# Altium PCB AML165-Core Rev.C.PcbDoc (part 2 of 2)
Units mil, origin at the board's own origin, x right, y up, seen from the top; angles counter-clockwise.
Board outline 3307.09 x 2047.24 mil, 2 copper layers (Top Layer, Bottom Layer), stack 12.8 mil thick; 150 components, 70 nets, 398 pads, 304 vias.
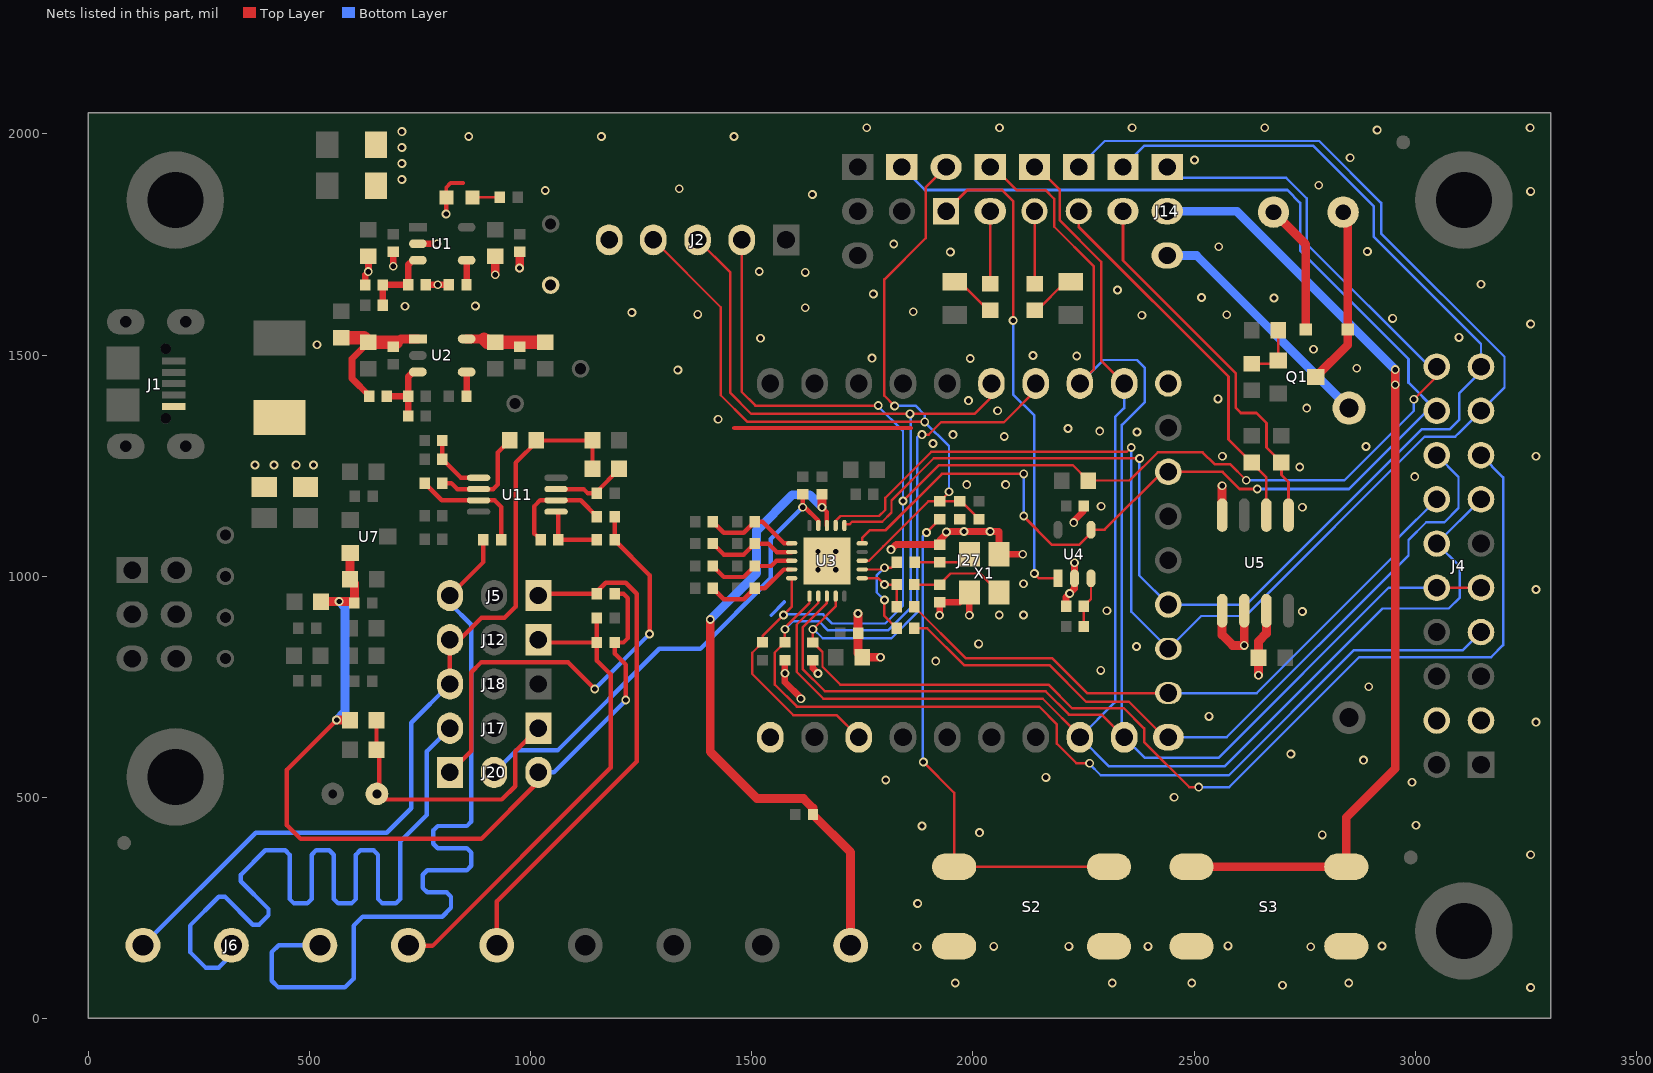
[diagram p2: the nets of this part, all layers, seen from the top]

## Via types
v1: diameter 20, hole 12, Top Layer to Bottom Layer, tented both sides, 304 vias

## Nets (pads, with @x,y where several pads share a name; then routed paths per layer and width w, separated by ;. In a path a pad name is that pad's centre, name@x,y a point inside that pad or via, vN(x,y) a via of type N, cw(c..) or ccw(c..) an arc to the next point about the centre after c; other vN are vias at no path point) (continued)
GND: BZ1.2 C1.2 C2.1 C3.2 C4.1 C5.1 C6.1 C18.1 C19.1 C21.2 C22.1 C25.1 C26.1 C32.2 C34.2 C43.1 D1.2 D2.1 J1.5 J2.5 J4.3 J4.4 J27.1 J27.18 LED1.2 R3.2 R6.1 R7.1 R9.1 R18.2 R42.1 S2.1 S2.4 S3.1 S3.4 T2.1 U1.2 U3.21 U4.2 U5.4 U5.5 U5.6 U5.7 X1.2 X1.4 | length 2518.1
  Top Layer w8: LED1.2@809.71,1856.54 809.71,1879.62 819,1888.91 848,1888.91
  Top Layer w10: v1(633,1688.54) v1@633.35,1688.88 ; v1(809,1818.91) 809,1855.82 LED1.2@809.71,1856.54 ; 1460,1334.91 1859.75,1335
  Top Layer w15: R3.2@626.03,1658.46 626.03,1681.57 v1(633,1688.54) ; v1@633.35,1688.88 C1.2@633.35,1723.5 ; v1(689.49,1700.54) C2.1@689.49,1733.5 ; U1.2@745.21,1751.54 v1(789,1751.54) ; C6.1@762.97,1659.02 v1(790.12,1659.02) C5.1@815,1659.02 ; R18.2@1575,810.32 v1(1575,780.43) 1575,760.16 1611,724.16 v1(1611,722.91) ; R9.1@1638.2,810 1638.2,791.8 v1(1650,780) ; v1(1815,1060) 1826.39,1071.39 C21.2@1924.82,1071.39 1924.82,1080.9 1940,1096.09 v1(1940,1099.91) 1941,1100.91 v1(1980,1100.91) v1(2039.03,1100.91) 2059.03,1100.91 X1.2@2059.03,1049.63 v1(2112.67,1049.63) ; v1@1924.82,911.51 C22.1@1924.82,941.02 1970.11,941.02 X1.4@1992.1,963.01 v1(1992.1,911.73) ; C26.1@2210.63,931.8 2210.63,952.77 v1(2218.77,960.91) 2229.72,971.85 U4.2@2229.72,994.93 v1(2229.72,1030.19) ; v1(2228,1120.92) 2228,1124.91 2250.63,1147.54 C25.1@2250.63,1158.54
  Top Layer w20: v1(920,1681.54) C3.2@920,1723.5 ; v1(975,1696.54) 975.52,1697.05 C4.1@975.52,1733.5 ; v1(1740.32,915.59) C18.1@1740.32,871.02 1740.32,826.28 C19.1@1750,816.59 v1(1791.32,816.59) ; U5.5@2563.63,945.28 U5.5@2563.63,921.97 2563.63,867.28 2587.37,843.54 v1(2613.63,843.54) U5.6@2613.63,921.97 ; U5.4@2563.63,1138.03 v1(2563.63,1204.28) ; v1(2645.91,776) C34.2@2645.91,815.91 2645.91,852.81 2663.63,870.54 U5.7@2663.63,921.97 ; BZ1.2@2679.81,1822.87 2752.5,1750.19 D2.1@2752.5,1557.76
  Bottom Layer w8: 1544,911.91 1574,941.91
  other v1: 3261,69.91 2700,75 1960,80 2315,80 2495,80 2850,80 1874,161.91 2764,162 2047,162.91 2217,162.91 2396,162.91 2577,164 2925,163.91 1875,260 3261,369.91 2790,415 2015,420 1885,435 3002,436.91 2455,500 2993,533.91 1803,538.91 2165,545 2883,583.91 2719,597.91 3273,669.91 2534,682.91 2895,749.91 2289,786.91 1916,807.91 2370,840.91 2013,846.91 1924.64,911.51 2059.57,911.96 2114.44,911.96 2745,919.91 2303,921.91 3273,969.91 2114.22,982.81 1650,1014.39 1690,1014.39 1650,1055.91 1690,1055.91 2745,1155.91 2290,1158 1986,1206.91 2074,1206.91 2999,1224.91 2739,1246.91 376.92,1251.09 419.92,1251.09 469.92,1251.09 508.92,1251.09 2564,1270.91 3273,1270.91 2889,1292.91 1910,1300 2071,1315.91 1955,1319.91 2371,1325.91 2287,1327.91 2215,1333.91 1424,1354.91 2056,1373.91 2755,1379.91 1990,1396.91 2554,1400.91 1333,1465.91 2868,1469.91 1994,1491.91 1772,1492.91 2235,1497.91 2136,1498.91 2770,1512.91 516.92,1523.09 1520,1537.91 3099,1539.91 3261,1569.91 2949,1582.91 2382,1589.91 2574,1590.91 1378,1591.91 1229,1595.91 1865,1597.91 1621,1606.91 715.92,1610.09 875,1610.91 2681,1628.91 2517,1629.91 1775,1637.91 2327,1646.91 3149,1660 1621,1686.91 1517,1688.91 1949,1732.91 2892,1734 2556,1744.91 1821,1750.91 1637,1862.91 3261,1869.91 1033,1871.91 1336,1875.91 2782,1883.91 708.93,1896.88 708.93,1932.92 2501,1940.91 2853,1945.91 708.93,1968.96 860,1994.22 1160,1994.22 1460,1994.22 708.93,2005 2914,2008.91 1760,2013.91 2060,2013.91 2360,2013.91 2660,2013.91 3260,2013.91
GPIO_KEY: J2.2 J4.20 J14.1 J27.3 R17.2 R41.1 U3.5 | length 4289.1
  Top Layer w5.5: J2.2@1477.48,1760.47 1477.48,1416.43 1508.21,1385.7 v1(1786,1385.7) ; U3.5@1590.28,995.4 1590.28,930.2 v1(1572,911.93) 1524.48,864.41 R17.2@1524.48,850.32 1501,826.84 1501,778.8 1593.9,685.91 1691.77,685.91 J27.3@1741.98,635.7 ; v1(1842,1169.91) 1923.07,1250.97 2225.86,1250.97 R41.1@2260.63,1216.2 2354.29,1216.2 2418,1279.91 2519.5,1279.91 2546.25,1253.16 2581.75,1253.16 v1(2618,1216.91) ; v1(2997,1399.91) 3048.82,1451.72 J4.20@3048.82,1473.62
  Bottom Layer w5.5: v1(1572,911.93) 1573.48,913.41 1661.36,913.41 1681.86,892.91 1801.75,892.91 1842,933.15 v1(1842,1169.91) 1842,1327.91 1786,1383.91 v1(1786,1385.7) ; J14.1@2439.37,1925 2463.46,1900.91 2708.09,1900.91 2755,1854 2755,1750.91 3032.28,1473.62 J4.20@3048.82,1473.62 ; v1(2618,1216.91) 2840,1216.91 2997,1373.91 v1(2997,1399.91)
GPIO_LED0: J4.9 J4.10 J9.1 J27.9 J27.20 U3.8 | length 3640.9
  Top Layer w5.5: U3.8@1670,955.05 1670,938.91 1615,883.91 1615,789.9 1665.26,739.63 2164.27,739.63 2217,686.91 2290.77,686.91 J27.9@2341.98,635.7 ; J9.1@2039.37,1925 2046.91,1925 2099,1872.91 2164,1872.91 2184,1852.91 2184,1789.91 2273,1700.91 2273,1466.72 J27.20@2241.98,1435.7 ; J4.10@3048.82,973.62 J4.9@3148.82,973.62
  Bottom Layer w5.5: J27.20@2241.98,1435.7 2294.93,1488.66 2371.25,1488.66 2389,1470.91 2389,1393.91 2337,1341.91 2337,640.68 J27.9@2341.98,635.7 2388.77,588.91 2555,588.91 2939.72,973.62 J4.10@3048.82,973.62
GPIO_LED1: J4.12 J4.13 J10.1 J27.8 J27.19 U3.7 | length 3642.7
  Top Layer w5.5: U3.7@1650.32,955.05 1650.32,939.22 1601.27,890.18 1601.27,783.73 1662.09,722.91 2158,722.91 2241.98,638.93 J27.8@2241.98,635.7 ; J10.1@2139.37,1925 2144.91,1925 2196,1873.91 2196,1804.91 2290,1710.91 2290,1487.68 J27.19@2341.98,1435.7
  Bottom Layer w5.5: J27.19@2341.98,1435.7 2341.98,1379.88 2321.53,1359.44 2321.53,715.26 J27.8@2241.98,635.7 2307.77,569.91 2569,569.91 2926,926.91 3076,926.91 3101,951.91 3101,1021.44 J4.12@3048.82,1073.62 J4.13@3148.82,1173.62
LED0: J9.2 R29.2 | length 164.3
  Top Layer w5.5: R29.2@2038.78,1660.91 2039.37,1661.49 J9.2@2039.37,1825
LED1: J10.2 R35.2 | length 164.4
  Top Layer w5.5: J10.2@2139.37,1825 2140,1824.37 R35.2@2140,1660.91
LM75_SCL: J4.17 J11.1 J27.12 U3.17 | length 3556.8
  Top Layer w5.5: U3.17@1689.69,1114.5 1689.69,1124.69 1701,1136 1788.11,1136 1801.87,1149.76 1801.87,1176.85 1906.24,1281.22 2348.32,1281.22 v1(2358,1290.91)
  Bottom Layer w5.5: J11.1@2239.37,1925 2298.28,1983.91 2783.04,1983.91 2923,1843.95 2923,1774.91 3202,1495.91 3202,1426.8 J4.17@3148.82,1373.62 3101.1,1325.91 3101,1325.91 3090.41,1315.31 3021.41,1315.31 2616,909.91 2516.18,909.91 J27.12@2441.98,835.7 2358,919.68 v1(2358,1290.91)
LM75_SDA: J4.19 J13.1 J27.13 U3.16 | length 3182
  Top Layer w5.5: U3.16@1709.37,1114.5 1711.87,1117 1721,1117 1727,1123 1795.09,1123 1816,1143.91 1816,1171 1911.41,1266.41 2376.49,1266.41 v1(2377,1265.91)
  Bottom Layer w5.5: J13.1@2339.37,1925 2387.28,1972.91 2770,1972.91 2906,1836.91 2906,1767.86 3148.82,1525.04 J4.19@3148.82,1473.62 3148.82,1462.72 3100,1413.91 3100,1353.91 3077.84,1331.74 3014.6,1331.74 2618.56,935.7 J27.13@2441.98,935.7 2376,1001.68 v1@2376,1265.91
MICROPORT_ADC1: J4.18 J7.1 J27.16 U3.15 U4.4 | length 3188.4
  Top Layer w6: U3.15@1749.72,1074.14 1749.72,1086.72 1766.91,1103.91 1803,1103.91 1930.32,1231.22 v1(2115,1231.22) ; v1(2115,1135.91) 2115,1134.94 2179.04,1070.91 2240,1070.91 2267.12,1098.02 U4.4@2267.12,1104.93 2297.56,1104.93 2428.33,1235.7 J27.16@2441.98,1235.7 2564.21,1235.7 2603,1196.91 v1(2643,1196.91)
  Bottom Layer w6: J7.1@1839.37,1925 1891.46,1872.91 2711.09,1872.91 2740,1844 2740,1735.91 2985,1490.91 2985,1437.44 J4.18@3048.82,1373.62 3026.64,1373.62 2849.93,1196.91 v1(2643,1196.91) ; v1(2115,1135.91) v1(2115,1231.22)
MICROPORT_CS: J2.3 J4.7 J27.22 R18.1 U3.6 | length 3869.9
  Top Layer w5.5: J2.3@1377.48,1760.47 1451.78,1686.17 1451.78,1414.13 1499,1366.91 v1(1858,1366.91) 2004,1366.91 2041.98,1404.88 J27.22@2041.98,1435.7 ; U3.6@1630.63,955.05 1630.63,939.54 1575,883.91 v1(1575,879.91) R18.1@1575,850.32 1552,827.32 1552,754.91 1602,704.91 2150,704.91 2190,664.91 2190,620.91 2234,576.91 v1(2264,576.91)
  Bottom Layer w5.5: v1(1575,879.91) 1593,897.91 1652,897.91 1672.66,877.25 1808.24,877.25 1859.75,928.76 1859.75,1365.16 v1(1858,1366.91) ; v1(2264,576.91) 2264,574.91 2289,549.91 2579,549.91 2862,832.91 3108.1,832.91 J4.7@3148.82,873.62
MICROPORT_I/O2: J4.14 J27.11 R21.1 | length 1461.6
  Top Layer w5.5: R21.1@1867.56,930.91 1984.56,813.91 2180,813.91 2258.21,735.7 J27.11@2441.98,735.7
  Bottom Layer w5.5: J27.11@2441.98,735.7 2641.79,735.7 2960,1053.91 2960,1084.8 J4.14@3048.82,1173.62
MICROPORT_I/O3: J4.16 J27.10 R19.1 | length 1707.8
  Top Layer w5.5: R19.1@1867.56,882.28 1896.63,882.28 1980,798.91 2173,798.91 2256,715.91 2353,715.91 2433.21,635.7 J27.10@2441.98,635.7
  Bottom Layer w5.5: J27.10@2441.98,635.7 2573.79,635.7 2985,1046.91 2985,1081.91 3025,1121.91 3066,1121.91 3098,1153.91 3098,1224.44 J4.16@3048.82,1273.62
MICROPORT_MOSI: J4.15 J27.21 R9.2 U3.9 | length 3435.7
  Top Layer w5.5: U3.9@1689.69,955.05 1689.69,931.39 v1(1638.2,879.91) R9.2@1638.2,850 1660,828.2 1660,795.1 1700.2,754.91 2171,754.91 2224.5,701.41 2341.5,701.41 2387,655.91 2387,625.13 2489.22,522.91 v1(2510.61,522.91) ; v1(1885,1320) 1900.09,1320 1928,1347.91 2070,1347.91 2141.98,1419.88 J27.21@2141.98,1435.7
  Bottom Layer w5.5: v1(1638.2,879.91) 1640,879.91 1660.41,859.5 1815.59,859.5 1874,917.91 1874,1314 1880,1320 v1(1885,1320) ; v1(2510.61,522.91) 2579.62,522.91 2873.62,816.91 3172,816.91 3199,843.91 3199,1223.44 J4.15@3148.82,1273.62
NetBZ1_1: BZ1.1 D2.2 Q1.3 | length 406.3
  Top Layer w20: Q1.3@2775.5,1450.59 2847.5,1522.6 D2.2@2847.5,1557.76 2847.5,1812.67 BZ1.1@2837.29,1822.87
NetC5_2: C5.2 U1.4 | length 55.2
  Top Layer w15: C5.2@855,1659.02 855.21,1659.23 U1.4@855.21,1714.13
NetC6_2: C6.2 R1.2 R3.1 U1.3 | length 174.2
  Top Layer w15: R1.2@666.03,1612.57 R3.1@666.03,1658.46 666.58,1659.02 C6.2@722.97,1659.02 722.97,1703.5 733.6,1714.13 U1.3@745.21,1714.13
NetC7_1: C7.1 C8.2 L1.2 R4.1 U2.1 | length 345.4
  Top Layer w15: C7.1@633.35,1528.91 596,1491.56 596,1446.91 635,1407.91 R4.1@635,1406.84
  Top Layer w20: C8.2@689.49,1518.91 706.9,1536.31 U2.1@745.21,1536.31
  Top Layer w30: L1.2@571.87,1538.91 623.35,1538.91 C7.1@633.35,1528.91 C8.2@696.54,1528.91
NetC9_1: C9.1 C10.2 L2.1 U2.5 | length 190.1
  Top Layer w20: U2.5@855.21,1536.31 894.6,1536.31 ; C10.2@975.52,1518.91 C10.2@975.52,1528.39
  Top Layer w30: 894.6,1536.31 902,1528.91 C9.1@920,1528.91 L2.1@1032.76,1528.91
NetC11_2: C11.2 U2.4 | length 54.7
  Top Layer w15: C11.2@855,1406.84 855.21,1407.05 U2.4@855.21,1461.5
NetC12_2: C12.2 R4.2 R5.1 U2.3 | length 163.2
  Top Layer w15: R4.2@675,1406.84 C12.2@722.97,1406.84 C12.2@723.12,1406.84 ; R5.1@723.12,1362 C12.2@723.12,1406.84 ; U2.3@745.21,1461.5 734.22,1461.5 723.12,1450.41 C12.2@723.12,1406.84
NetC16_2: C16.2 R8.2 U3.1 | length 219.1
  Top Layer w10: R8.2@1411.91,1122.77 1436.78,1097.91 1482.05,1097.91 C16.2@1506.91,1122.77 1524.23,1122.77 1572.86,1074.14 U3.1@1590.28,1074.14
NetC17_2: C17.2 R12.2 U3.2 | length 206.9
  Top Layer w10: R12.2@1411.91,1073.68 1436.78,1048.81 1482.05,1048.81 C17.2@1506.91,1073.68 1537.32,1073.68 1556.54,1054.46 U3.2@1590.28,1054.46
NetC21_1: C21.1 R11.2 X1.3 | length 131.3
  Top Layer w6: R11.2@1868.35,1031.39 C21.1@1924.82,1031.39 1973.87,1031.39 X1.3@1992.1,1049.63
NetC22_2: C22.2 R14.1 X1.1 | length 219.6
  Top Layer w5.5: R14.1@1867.56,980.91 1924.7,980.91 C22.2@1924.82,981.02 1949.7,1005.91 2016.14,1005.91 X1.1@2059.03,963.01
NetC23_2: C23.2 R13.2 U3.3 | length 203.9
  Top Layer w10: R13.2@1411.91,1022.96 1436.78,998.09 1482.05,998.09 C23.2@1506.91,1022.96 1543.96,1022.96 1555.77,1034.77 U3.3@1590.28,1034.77
NetC24_2: C24.2 R16.2 U3.4 | length 216.6
  Top Layer w10: R16.2@1411.91,972.61 1436.78,947.74 1482.05,947.74 C24.2@1506.91,972.61 1529.61,972.61 1572.09,1015.09 U3.4@1590.28,1015.09
NetC26_2: C26.2 R26.1 U4.3 | length 115.5
  Top Layer w5.5: R26.1@2250.63,886.29 C26.2@2250.63,931.8 2267.12,948.29 U4.3@2267.12,994.93
NetC27_1: C27.1 R24.1 U11.6 | length 245.7
  Top Layer w10: C27.1@800.37,1209.73 821.01,1209.73 833.86,1196.88 U11.6@882.34,1196.88 915.38,1196.88 925.62,1207.12 925.62,1279.54 R24.1@952.85,1306.77
NetC27_2: C27.2 R25.2 U11.7 | length 269.4
  Top Layer w10: C27.2@760.37,1209.73 798.8,1171.29 U11.7@882.34,1171.29 918.45,1171.29 933.35,1156.39 R25.2@933.35,1082.09
NetC36_1: C36.1 R30.2 U11.3 | length 173.2
  Top Layer w10: U11.3@1057.53,1196.88 1119.82,1196.88 1129.62,1187.09 C36.1@1149.93,1187.09 1149.93,1191.41 1199.93,1241.41 R30.2@1199.93,1243.09
NetC39_1: C39.1 R50.2 U11.2 | length 244.1
  Top Layer w10: C39.1@1022.76,1082.09 1008.62,1096.23 1008.62,1158.49 1021.42,1171.29 U11.2@1057.53,1171.29 1113.23,1171.29 R50.2@1149.93,1134.59
NetC39_2: C39.2 R48.1 U11.1 | length 153
  Top Layer w10: U11.1@1057.53,1145.7 1062.76,1140.48 C39.2@1062.76,1082.09 R48.1@1149.93,1082.09
NetJ14_2: J14.2 S3.2 S3.3 | length 2217.7
  Top Layer w20: S3.3@2494.25,343 S3.2@2844.25,343 2844.25,454.25 2955,565 v1(2955,1432.91) v1(2955,1466.91)
  Bottom Layer w20: J14.2@2439.37,1825 2596.91,1825 v1(2955,1466.91) v1(2955,1432.91)
NetJ14_3: J14.3 R40.2 | length 554.2
  Bottom Layer w20: J14.3@2439.37,1725 2505.63,1725 R40.2@2850.63,1380
NetLED1_1: LED1.1 R2.1 | length 61.8
  Top Layer w5.5: LED1.1@868.77,1856.54 R2.1@930.57,1856.54
NetLED2_2: LED2.2 R29.1 | length 106.9
  Top Layer w5.5: LED2.2@1958.78,1665.92 1969.98,1665.92 2035,1600.91 R29.1@2038.78,1600.91
NetLED3_2: LED3.2 R35.1 | length 109.6
  Top Layer w5.5: R35.1@2140,1600.91 2145,1600.91 2210.02,1665.92 LED3.2@2221,1665.92 LED3.2@2222.66,1665.92
NetQ1_1: Q1.1 R28.1 R34.2 | length 130.7
  Top Layer w6: R28.1@2630.91,1480.41 2682.91,1480.41 Q1.1@2690.5,1487.99 2690.5,1555.85 R34.2@2690.44,1555.91
NetR23_2: R23.2 R31.2 U11.5 | length 145.4
  Top Layer w10: R31.2@799.85,1259.89 R31.2@800.37,1259.37 ; R23.2@800.37,1306.77 R31.2@800.37,1264.25 R31.2@800.37,1259.37 ; U11.5@882.34,1222.47 842.47,1222.47 805.57,1259.37 R31.2@800.37,1259.37
NetR27_1: R27.1 S2.2 S2.3 | length 1181.3
  Top Layer w5.5: v1(1888,579.91) 1957.6,510.31 S2.3@1957.6,343 S2.2@2307.6,343 ; v1(1895,1098.83) R27.1@1925.26,1129.09
  Bottom Layer w5.5: v1(1888,579.91) 1886.89,581.02 1886.89,1090.72 v1(1895,1098.83)
NRST_WDT: J8.1 U4.1 | length 1101.6
  Top Layer w6: J8.1@1939.37,1825 1987.27,1872.91 2066,1872.91 2091,1847.91 v1(2091,1577.91) ; v1(2139,1005.91) 2149.98,994.93 U4.1@2192.32,994.93
  Bottom Layer w6: v1(2091,1577.91) 2091,1410.91 2139,1362.91 v1(2139,1005.91)
NTC_IN: C35.2 J17.1 R15.1 RV2.2 | length 652.6
  Top Layer w10: R15.1@651.57,674.61 C35.2@651.57,607.61 657.57,601.61 657.57,507.61 RV2.2@670.28,494.91 ; RV2.2@665.28,494.91 RV2.2@670.28,494.91 ; J17.1@1017.52,656.14 965,603.62 965,524.91 935,494.91 RV2.2@670.28,494.91
PD0/OSC_IN/I2C1_SDA: R14.2 R21.2 U3.11 | length 133.8
  Top Layer w5.5: U3.11@1749.72,995.4 1785.5,995.4 v1(1800,980.91) R14.2@1827.56,980.91 R21.2@1827.56,930.91
PD1/OSC_OUT/I2C1_SCL: R11.1 R19.2 U3.12 | length 248.2
  Top Layer w5.5: U3.12@1749.72,1015.09 1796.06,1015.09 v1(1800,1019.02) 1815.98,1019.02 R11.1@1828.35,1031.39 ; v1(1800,945.91) 1800,909.83 R19.2@1827.56,882.28
  Bottom Layer w5.5: v1(1800,945.91) 1782.25,963.66 1782.25,1001.27 v1(1800,1019.02)
R\E\S\E\T\: C32.1 J2.4 J8.2 R22.1 R27.2 U3.13 | length 2148
  Top Layer w5.5: J2.4@1277.48,1760.47 1430,1607.95 1430,1408.91 1490,1348.91 v1(1891,1348.91) ; U3.13@1749.72,1034.77 1764.77,1034.77 1797.25,1067.25 1797.25,1067.35 1898.98,1169.09 R27.2@1925.26,1169.09 ; v1(1823,1384.91) 1800,1407.91 1800,1671 1893,1764 1893,1878.63 J8.2@1939.37,1925 ; v1(1946,1190.91) 1946,1189.83 R27.2@1925.26,1169.09 ; R22.1@2014,1129.09 1974,1169.09 C32.1@1970.16,1169.09 R27.2@1925.26,1169.09
  Bottom Layer w5.5: v1(1823,1384.91) 1871,1384.91 1891,1364.91 v1(1891,1348.91) 1946,1293.91 v1(1946,1190.91)
REF_2.5V: C29.2 C31.2 J20.3 R15.2 R20.1 R32.2 R43.2 U7.2 | length 1998.7
  Top Layer w10: v1(561.48,674.61) 448.71,561.84 448.71,437.2 480,405.91 888.52,405.91 1017.52,534.91 J20.3@1017.52,556.14 ; R20.1@1190,960 1210,960 1220,950 1220,860 1210,850 R43.2@1190,850 1190,825 1215,800 v1(1215,719.91)
  Top Layer w20: R32.2@526.16,942.61 v1(567,942.61) C31.2@591.57,942.61 ; v1(561.48,674.61) R15.2@591.57,674.61 ; U7.2@592.32,1052.02 591.78,1051.49 C29.2@591.78,992.81 601.57,983.02 C31.2@601.57,939.37
  Bottom Layer w10: J20.3@1017.52,556.14 1052.24,556.14 1215,718.91 v1(1215,719.91)
  Bottom Layer w20: v1(561.48,674.61) 580,693.13 580,929.61 v1(567,942.61)
REF_ADC: C15.2 J20.2 U3.19 | length 1087
  Top Layer w5.5: C15.2@1615,1184.7 C15.2@1615,1185.91
  Top Layer w10: C15.2@1615,1184.7 v1(1615,1155.91) 1620.09,1155.91 1650.32,1125.68 U3.19@1650.32,1114.5
  Bottom Layer w10: J20.2@917.52,556.14 967.28,605.91 1061,605.91 1291,835.91 1383.91,835.91 1543,995 1543,1083.91 v1(1615,1155.91)
REF_RTD: J20.1 R48.2 R50.1 | length 1033.5
  Top Layer w10: J20.1@817.52,556.14 866,604.62 866,782.91 888,804.91 1085.09,804.91 v1(1145,745) ; R50.1@1189.93,1134.59 R48.2@1189.93,1082.09 1189.93,1080.97 1269,1001.91 v1(1269,869)
  Bottom Layer w10: v1(1145,745) v1(1269,869)
RTD_A: J5.3 J6.3 R25.1 | length 1918.8
  Top Layer w10: J5.3@817.52,956.14 893.35,1031.97 R25.1@893.35,1082.09
  Bottom Layer w10: J6.3@523.62,165.35 430.35,165.35 415,150 415,85 430,70 580,70 600,90 600,210 620,230 800,230 820,250 820,275 810,285 766,285 756,295 756,325 766,335 856,335 866,345 866,375 856,385 790,385 780,395 780,425 790,435 856,435 866,445 866,889.91 817.52,938.39 J5.3@817.52,956.14
RTD_B: J6.2 J17.3 | length 1920
  Bottom Layer w10: J6.2@323.62,165.35 323.62,143.62 295,115 265,115 230,150 230,210 294.9,274.9 309.04,274.9 371.97,211.97 386.11,211.97 407.32,233.18 407.32,247.32 344.39,310.25 344.39,324.39 400,380 445,380 455,370 455,270 465,260 495,260 505,270 505,370 515,380 545,380 555,370 555,270 565,260 595,260 605,270 605,370 615,380 645,380 655,370 655,270 665,260 695,260 705,270 705,400 765,460 765,603.62 J17.3@817.52,656.14
RTD_C: J6.1 J12.3 J18.3 R24.2 R30.1 R49.1 | length 1919.1
  Top Layer w10: J18.3@817.52,756.14 J12.3@817.52,856.14 839.24,856.14 889,905.91 941,905.91 966,930.91 966,1256.18 R24.2@1016.59,1306.77 ; R24.2@1012.85,1306.77 R24.2@1016.59,1306.77 ; R30.1@1139.93,1243.09 R49.1@1139.93,1306.77 R24.2@1016.59,1306.77
  Bottom Layer w10: J6.1@123.62,165.35 378.27,420 675,420 730,475 730,668.62 J18.3@817.52,756.14
SCL: J11.2 R39.1 U5.2 | length 862.7
  Top Layer w6: J11.2@2239.37,1825 2239.37,1789.54 2578,1450.91 2578,1309.09 R39.1@2630,1257.09 2663.63,1223.46 U5.2@2663.63,1138.03
SDA: J13.2 R36.1 U5.1 | length 862.5
  Top Layer w6: J13.2@2339.37,1825 2339.37,1713.54 2594.37,1458.54 2594.37,1380.54 2606,1368.91 2641,1368.91 2664,1345.91 2664,1290.77 R36.1@2697.68,1257.09 2697.68,1228.85 2713.63,1212.91 U5.1@2713.63,1138.03
TC_A: J3.2 J5.1 R20.2 | length 1173.5
  Top Layer w10: J3.2@923.62,165.35 923.62,264.53 1240,580.91 1240,960 1215,985 1170,985 1149.7,964.7 R20.2@1149.7,960 ; J5.1@1017.52,956.14 1021.38,960 R20.2@1149.7,960 ; R20.2@1150,960 R20.2@1149.7,960
TC_B: J3.1 J12.1 R43.1 R44.1 | length 1113.9
  Top Layer w10: J3.1@726.2,165.35 J3.1@723.62,165.35 725.07,163.91 778,163.91 1181.18,567.09 1181.18,777.73 1150,808.91 R43.1@1150,850 1023.66,850 J12.1@1017.52,856.14 ; R43.1@1143.86,856.14 1150,856.14 R44.1@1150,905.29
VREFOUT: C20.2 C33.2 J16.2 U3.18 | length 1442.3
  Top Layer w10: v1(1659.04,1155.91) 1670,1144.95 U3.18@1670,1114.5
  Top Layer w20: v1(1406,901.91) 1406,602.91 1512,496.91 1617,496.91 1638.52,475.39 C33.2@1638.52,460.91 1723.62,375.8 J16.2@1723.62,165.35 ; v1(1659.04,1155.91) C20.2@1659.04,1184.7
  Bottom Layer w20: v1(1406,901.91) 1406.42,901.91 1511,1006.48 1511,1102.91 1592,1183.91 1631.04,1183.91 v1(1659.04,1155.91)
pads on no net: HOLE2.1 HOLE3.1 HOLE4.1 J1.0 J1.2 J1.3 J1.4 J4.5 J4.6 J4.8 J4.11 J27.2 J27.4 J27.5 J27.6 J27.7 J27.14 J27.15 J27.17 J27.23 J27.24 J27.25 MARK3.0 MARK4.0 MARK5.0 U5.3

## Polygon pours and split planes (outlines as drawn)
AGND on Top Layer "AGND_L01_P061" (solid, remove dead copper, pour order 61): 0,1151.91 532,1151.91 559,1178.91 559,1535.91 586,1562.91 1127,1562.91 1388,1301.91 1390,1299.91 1441,1299.91 1780,1299.91 1806,1273.91 1806,1157.91 1762,1113.91 1660,1113.91 1649,1113.91 1616,1080.91 1608.98,1073.88 1608.98,1026.91 1608.98,1021.88 1543,955.91 1454,866.91 1454,597.91 1454,589.91 1515,528.91 1520,523.91 1700,523.91 1701,523.91 1818,406.91 1818,0 0,0
GND on Top Layer "GND_L01_P069" (solid, remove dead copper, pour order 69): 358,1181.91 520,1181.91 528,1189.91 528,1546.91 543,1561.91 574,1592.91 734,1592.91 1139,1592.91 1402,1329.91 1792,1329.91 1832,1289.91 1836,1285.91 1836,1151.91 1836,1145.91 1818,1127.91 1774,1083.91 1711,1083.91 1661,1083.91 1649,1071.91 1639,1061.91 1639,1021.91 1639,1012.91 1554,927.91 1484,857.91 1484,601.91 1532,553.91 1713,553.91 1830,436.91 1848,418.91 1848,0 3306.99,0 3307.09,2047.24 562.34,2047.24 510,1994.91 510,1730.91 510,1726.91 423,1639.91 358,1574.91 358,1293.91 358,1231.91
GND on Bottom Layer "GND_L02_P065" (solid, remove dead copper, pour order 65): 371.92,1232 516,1232 528,1244 528,1546.91 543,1561.91 574,1592.91 734,1592.91 1139,1592.91 1402,1329.91 1792,1329.91 1832,1289.91 1836,1285.91 1836,1151.91 1836,1145.91 1818,1127.91 1774,1083.91 1711,1083.91 1661,1083.91 1649,1071.91 1639,1061.91 1639,1021.91 1639,1012.91 1554,927.91 1484,857.91 1484,601.91 1532,553.91 1713,553.91 1830,436.91 1848,418.91 1848,0 3306.99,0 3307.09,2047.24 562.34,2047.24 510,1994.91 510,1730.91 510,1726.91 423,1639.91 358,1574.91 358,1293.91 358,1245.93
AGND on Bottom Layer "AGND_L02_P063" (solid, remove dead copper, pour order 63): 0,1151.91 532,1151.91 559,1178.91 559,1535.91 586,1562.91 1127,1562.91 1388,1301.91 1390,1299.91 1441,1299.91 1780,1299.91 1806,1273.91 1806,1157.91 1762,1113.91 1660,1113.91 1649,1113.91 1616,1080.91 1608.98,1073.88 1608.98,1026.91 1608.98,1021.88 1543,955.91 1454,866.91 1454,597.91 1454,589.91 1515,528.91 1520,523.91 1700,523.91 1701,523.91 1818,406.91 1818,0 0,0

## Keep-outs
Keep-Out Layer:
  the board outline again, w5

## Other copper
Top Layer:
  rectangle: 2549.94,976 2841.63,1084
  rectangle: 2764.63,800 2926.63,1260
  pour cut-out: 2286.8,1883.47 2399.57,1883.47 2415,1898.91 2415,1939.91 2387,1967.91 2280,1967.91 2271,1958.91 2272,1957.91 2272,1883.91
  region net GND: 615.63,1739.54 696,1739.54 718,1761.54 754.37,1761.54 760.37,1755.54 760.37,1745.9 756,1741.54 731,1741.54 708,1718.54 618.57,1718.54 615,1722.1 615,1738.91
  region net 3.3V: 845,1779.54 887,1779.54 895,1771.54 1060.91,1771.54 1075,1785.63 1075,1816.54 1065,1826.54 893,1826.54 865,1798.54 844,1798.54 840,1794.54 840,1784.54
  region net GND: 528,1276.59 528,1188.28 519.81,1180.09 368.82,1180.08 358,1190.91 358,1269.58 368.5,1280.09 524.5,1280.09
  region net AGND: 535.82,1154.09 360.5,1154.09 350.5,1144.09 350.5,1077.09 367.5,1060.09 524.5,1060.09 538.5,1074.09 538.5,1151.4
  region net 5V: 219,1478.91 243,1454.91 328,1454.9 374,1500.9 439,1500.91 485,1546.91 523,1584.91 574.72,1584.91 590,1600.19 590,1746.91 579,1757.9 541,1757.91 522,1738.9 423,1639.91 341,1557.91 277,1493.91 188,1493.91 185,1490.91 185,1482.91 189,1478.91
  region net 5V: 581.88,1732.88 615.75,1766.75 698.85,1766.76 711,1778.91 756.37,1778.91 762,1784.54 762,1794.91 758,1798.91 724,1798.91 710,1812.91 596,1812.9 535,1751.91 535,1733.51
  region net GND: 183,1391.91 220,1391.91 242,1413.91 356,1413.91 372,1397.91 482,1397.91 488,1391.91 488,1328.91 479,1319.91 344,1319.91 288,1375.9 184,1375.91 179,1380.91 179,1387.91
  region net EARTH1: 565,2000 541.01,2024 42.99,2023.99 36,2017 36,1289.91 61,1264.91 239,1264.91 256,1281.91 256,1306.91 241,1321.91 125,1321.9 115,1331.9 115,1537.91 124,1546.91 240,1546.91 260,1566.91 260,1633.91 412,1785.9 479.1,1853 546.09,1853 565,1871.9
  region net GND: 694,1851 633,1851 628.11,1855.89 628.11,2004.11 647.99,2024 702,2024 722.11,2003.89 722.11,1879.11
  region net GND: 344,1319.91 358,1305.91 358,1294.91 514,1294.91 526,1306.91 526,1385.91 514,1397.91 348,1397.91 344,1393.91
  region net AGND: 1677,1219 1682,1214 1682,1165 1691,1156 1710,1156 1717,1163 1717,1198 1698.8,1216.21 1698.8,1238.2 1694,1243 1690,1239 1689,1239 1677,1227
  pour cut-out: 678,2023 678,1832 661,1815 613,1815 598,1830 598,2004 619,2025 676,2025
  pour cut-out: 1786.8,1883.47 1798.47,1883.47 1800,1885 1800,1925 1795,1930 1780,1930 1780,1890.27
  pour cut-out: 1010,790 1010,725 1000,715 978.61,715 972.99,720.62 972.99,787.99 980,795 1005,795
Bottom Layer:
  pour cut-out: 2489.8,1969.53 2489.8,1823.91 1739.37,1823.91 1739.37,1969.53 1788.94,1969.53
  pour cut-out: 3194.74,1284.59 3194.74,1477.26 3157,1515 3147,1505 3029,1505 2989,1465 2989,1302 3024,1267 3024,1180 3059,1145 3179,1145 3195,1161 3195,1167
  region net EARTH1: 565,2000 541.01,2024 42.99,2023.99 36,2017 36,1289.91 61,1264.91 239,1264.91 256,1281.91 256,1306.91 241,1321.91 125,1321.9 115,1331.9 115,1537.91 124,1546.91 240,1546.91 260,1566.91 260,1633.91 412,1785.9 479.1,1853 546.16,1853 565,1871.83
  pour cut-out: 647.99,2024 625,2001 625,1841.91 506.47,1723.38 505.2,1724.65 505.2,1964.97 564.53,2024.3
  pour cut-out: 123.62,113.54 521.1,113.54 627.56,220 814.51,220 837.33,242.82 837.33,275 883.33,321 883.33,521.67 875,530 810,530 685.91,405.91 370.91,405.91 115,150 115,122.16

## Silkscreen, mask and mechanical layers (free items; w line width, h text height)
Top Overlay:
  region: 3387.82,2176.31 3387.82,2164.31 3242.82,2164.31 3242.82,2137.31 3387.82,2137.31 3387.82,2126.31 3449.82,2151.31
  lines w8: 3242.82,2137.31 3387.82,2137.31 3387.82,2126.31 3449.82,2151.31 3387.82,2176.31 3387.82,2164.31 3242.82,2164.31 3242.82,2137.31
  text "5V" at 1627,1957.91 h30
  text "PWR" at 780,1955.91 h60
  text "PA13" at 2504,1938 h30
  text "GND" at 1156.01,1866.13 h36 r90
  text "RST" at 1256.01,1866.13 h36 r90
  text "CLK" at 1356.01,1866.13 h36 r90
  text "DIO" at 1456.01,1866.13 h36 r90
  text "3.3V" at 1556.01,1866.13 h36 r90
  text "Vmic" at 1672,1806.91 h30 r90
  text "KEY" at 2500,1776.91 h30
  text "RES" at 2504,1708.91 h30
  text "3.3VA" at 1630,1621.91 h30
  text "AML165-Core" at 1151,1436.91 h55
  text "200723 Rev.C" at 1150,1389.91 h55
  text "P/N:13.01.04993" at 1132,1347.91 h50
  text "AP1" at 57,1198.91 h30
  text "CA0" at 167,1198.91 h30
  text "AN1" at 57,1143.91 h30
  text "CA1" at 167,1143.91 h30
  text "AP1" at 57,1088.91 h30
  text "CA2" at 167,1088.91 h30
  text "MicroPort" at 1678,510.91 h50
  text "MinPort" at 2953,429.91 h50
  text "RTDC" at 149.11,378.31 h30
  text "RTDB" at 306.71,377.82 h30
  text "RTDA" at 464.31,377.82 h30
  text "TC-" at 745.31,378.31 h30
  text "TC+" at 867,378.31 h30
  text "Br+" at 1153,377.82 h30
  text "Br-" at 1284.16,377.82 h30
  text "AGND" at 1537.41,378.36 h30
  text "VCC" at 1675.41,378.31 h30
  text "KEY/RES" at 2595,60 h30
  text "RST" at 2095,55.72 h30
Bottom Overlay:
  lines w8: 750,1035.91 1435,1035.91 1435,475.91 735,475.91 735,1035.91 755,1035.91
  text "PA0" at 1876,1987.91 h30
  text "PB3" at 2176,1987.91 h30
  text "PA5" at 2276,1987.91 h30
  text "PB4" at 2076,1987.36 h30
  text "PA4" at 2376,1987.36 h30
  text "5V" at 1671,1913.91 h30
  text "PA13" at 2606,1911.91 h30
  text "Vmic" at 1671,1827.91 h30
  text "KEY" at 2589,1815 h30
  text "BEEP" at 1894,1729.53 h30
  text "WDT" at 1997,1729.53 h30
  text "LED0" at 2107,1730.01 h30
  text "LED1" at 2209,1729.53 h30
  text "SCL" at 2297,1730.01 h30
  text "SDA" at 2389,1730.01 h30
  text "RES" at 2589,1715 h30
  text "3.3V" at 1671,1661.91 h30
  text "PA13" at 2995,1460 h30
  text "PA4" at 3291,1460 h30
  text "GND" at 2597,1422.46 h30
  text "PA0" at 2995,1360 h30
  text "PA5" at 3291,1360 h30
  text "NC" at 2594,1322.46 h30
  text "NC" at 1732.09,1316.58 h30 r270
  text "NC" at 1832.09,1316.58 h30 r270
  text "NC" at 1932.09,1316.58 h30 r270
  text "PB5" at 2132.09,1295.53 h30 r270
  text "PB3" at 2332.09,1296.07 h30 r270
  text "PB4" at 2232.09,1295.24 h30 r270
  text "3.3V" at 1632.09,1288.33 h30 r270
  text "Vmic" at 1527,1274.48 h30 r270
  text "PA14" at 2032.09,1272.86 h30 r270
  text "PD1" at 2995,1260 h30
  text "PB5" at 3291,1260 h30
  text "PA0" at 2594,1222.46 h30
  text "PD0" at 2995,1160 h30
  text "PB3" at 3291,1160 h30
  text "NC" at 2594,1122.46 h30
  text "PB3   TXD" at 2996,1060 h30
  text "NC" at 3291,1060 h30
  text "NC" at 2594,1022.46 h30
  text "PB4   RXD" at 2996,960 h30
  text "PB4" at 3291,960 h30
  text "RTA" at 1180,945.91 h30
  text "AP1" at 1279,945.91 h30
  text "TCA" at 1400,945.91 h30
  text "PA4" at 2594,922.46 h30
  text "NC" at 2996,860 h30
  text "PA14" at 3291,860 h30
  text "RTC" at 1179.29,844.66 h30
  text "AN1" at 1279.79,844.66 h30
  text "TCB" at 1398.57,844.66 h30
  text "PA5" at 2594,822.46 h30
  text "NC" at 3291,760 h30
  text "NC" at 2996,759 h30
  text "RTC" at 1179.29,742.16 h30
  text "AN2" at 1286.22,742.16 h30
  text "AGND" at 1415.07,742.16 h30
  text "PD0" at 2594,722.46 h30
  text "GND" at 1527.86,695 h30 r270
  text "NC" at 1628.09,695 h30 r270
  text "PA13" at 1728.09,695 h30 r270
  text "NC" at 1828.09,695 h30 r270
  text "NC" at 1928.09,695 h30 r270
  text "NC" at 2028.09,695 h30 r270
  text "NC" at 2128.09,695 h30 r270
  text "PB3" at 2227.09,695 h30 r270
  text "PB4" at 2328,695 h30 r270
  text "GND" at 3291,660 h30
  text "GND" at 2996,659 h30
  text "RTB" at 1178.57,641.5 h30
  text "AP2" at 1285.43,641.5 h30
  text "NTC" at 1398.5,641.5 h30
  text "PD1" at 2594,622.46 h30
  text "5V" at 2994,560 h30
  text "3.3V" at 3291,560 h30
  text "RTD" at 1178.57,540.91 h30
  text "REF" at 1281.57,540.91 h30
  text "2.5V" at 1404.71,540.91 h30
  text "RTDB" at 372,238.9 h30
  text "RTDA" at 575,238.9 h30
  text "Br+" at 1155,238.9 h30
  text "Br-" at 1347,238.9 h30
  text "RTDC" at 173,238.36 h30
  text "TC-" at 754,238.36 h30
  text "TC+" at 959.57,238.36 h30
  text "AGND" at 1562,238.36 h30
  text "VCC" at 1760.57,238.36 h30
Mechanical 1:
  lines w0.5: 0,-2047.24 0,-2244.09 6692.91,-2244.09 6692.91,-2047.24 ; 0,2047.24 0,2244.09 6692.91,2244.09 6692.91,2047.24
  lines w5: 6752.74,-2083.34 6716.74,-2047.34 ; 6752.74,-2011.34 6716.74,-2047.34 ; 6752.74,-36.09 6716.74,-0.09 ; 6752.74,35.91 6716.74,-0.09 ; 6752.74,2011.15 6716.74,2047.15 ; 6752.74,2083.15 6716.74,2047.15 ; 6970.74,-2047.34 6716.74,-2047.34 ; 6970.74,-0.09 6716.74,-0.09 ; 6970.74,2047.15 6716.74,2047.15 ; 0,0 3307.09,0 ; 0,0 0,2047.24 3307.09,2047.24 ; 0,0 0,-2047.24 3307.09,-2047.24 ; 3307.09,-2047.24 3385.83,-2047.24 ; 3307.09,-2047.24 3307.09,0 ; 3307.09,0 3385.83,0 ; 3307.09,0 3307.09,2047.24 ; 3307.09,2047.24 3385.83,2047.24 ; 3385.83,-2047.24 3385.83,0 ; 3385.83,-2047.24 6692.91,-2047.24 6692.91,0 ; 3385.83,0 3385.83,2047.24 ; 3385.83,0 6692.91,0 ; 3385.83,2047.24 6692.91,2047.24 6692.91,0
  text "VCUT" at 7012.74,2018.15 h60
  text "挖空" at 3365,1006.91 h60 r90
  text "F" at 5015.74,827.91 h500
  text "F" at 1569,802.24 h500
  text "VCUT" at 7012.74,-29.09 h60
  text "挖空" at 3367,-913.09 h60 r90
  text "F" at 1582,-1282.24 h500
  text "F" at 5007.74,-1282.24 h500
  text "VCUT" at 7012.74,-2076.34 h60
Mechanical 2:
  drawing of 637 lines, arcs and shapes, not listed
  text "PCB加工工艺要求" at 9259,2054 h280
  text "mm x" at 8456,1868 h100
  text "mm" at 9066,1868 h100
  text "170" at 8121,1859 h100
  text "114" at 8731,1859 h100
  text "IPC-600E   IPC-6011/12" at 10224,1858 h100
  text "IPC-Ⅱ" at 11559,1857 h100
  text "IPC-Ⅲ" at 12059,1857 h100
  text "尺寸" at 7567.7,1840.14 h150
  text "验收标准" at 9567.7,1840.14 h150
  text "FR4 TG140" at 8274,1658 h100
  text "FR4 TG170" at 9174,1658 h100
  text "生益有胶材料" at 10074,1658 h100
  text "MEGTRON6" at 10974,1658 h100
  text "其他：" at 11874,1658 h100
  text "板材" at 7566.27,1639.93 h150
  text "单面" at 8274,1458 h100
  text "2" at 8974,1458 h100
  text "4" at 9674,1458 h100
  text "6" at 10374,1458 h100
  text "8" at 11074,1458 h100
  text "10" at 11774,1458 h100
  text "板层" at 7566.27,1439.71 h150
  text "0.4mm" at 8274,1258 h100
  text "0.6mm" at 8824,1258 h100
  text "0.8mm" at 9374,1258 h100
  text "1.0mm" at 9924,1258 h100
  text "1.2mm" at 10474,1258 h100
  text "1.4mm" at 11024,1258 h100
  text "1.6mm" at 11574,1258 h100
  text "1.8mm" at 12124,1258 h100
  text "2.0mm" at 12674,1258 h100
  text "板厚" at 7566.27,1239.5 h150
  text "1/2OZ" at 9504,1058 h100
  text "1OZ" at 10004,1058 h100
  text "2OZ" at 10504,1058 h100
  text "（完成铜厚）" at 8507.3,1045.25 h130
  text "外层" at 8231.05,1039 h150
  text "铜厚" at 7566.13,1037.71 h150
  text "白色" at 8724,858 h100
  text "其他：" at 9424,858 h100
  text "丝印颜色" at 7566.13,838.5 h150
  text "绿色" at 8724,658 h100
  text "黑色" at 9424,658 h100
  text "红色" at 10124,658 h100
  text "蓝色" at 10824,658 h100
  text "黄色" at 11524,658 h100
  text "其他：" at 12224,658 h100
  text "（亮光）" at 8106.5,645.4 h130
  text "阻焊颜色" at 7566.13,638.29 h150
  text "沉镍金" at 8724,458 h100
  text "无铅喷锡" at 9424,458 h100
  text "电镀镍金" at 10124,458 h100
  text "电镀软金" at 10824,458 h100
  text "化学沉锡" at 11524,458 h100
  text "光板" at 12224,458 h100
  text "OSP" at 12744,458 h100
  text "表面处理工艺" at 7566.13,437.07 h150
  text "无" at 8724,259 h100
  text "按键镀硬金" at 9144,259 h100
  text "金手指" at 9864,259 h100
  text "半孔工艺" at 10554,259 h100
  text "FPCB补强" at 11244,259 h100
  text "树脂塞孔" at 11934,259 h100
  text "电镀填孔" at 12624,259 h100
  text "特殊工艺" at 7566.13,237.86 h150
  text "是，但双面开窗除外" at 8724,58 h100
  text "否" at 9869,58 h100
  text "按文件" at 10569,58 h100
  text "是否阻焊塞孔" at 7566.27,37.21 h150
  text "非拼板" at 8724,-142 h100
  text "拼板" at 9424,-142 h100
  text "分成单板交货" at 10124,-142 h100
  text "交货方式" at 7566.13,-162 h150
  text "Gerber输出：英制、相对零点、抑制前导零、精度2:5" at 7569,-336 h120
  text "Ver 20.03.30" at 12264,-403 h120
  text "NC Drill输出：英制、相对零点、抑制前导零、精度2:4" at 7569,-476 h120
  text "R" at 12615,-605.5 h25
  text "其他说明" at 7564,-651 h150
  text "94V-0" at 12685,-661 h46
  text "标识样式>>>" at 11824,-716 h120
  text "CTI>=175" at 12529,-746 h86.61
  text "1." at 7539,-786 h120
  text "机械1层(*.GM1)为外形铣边；若存在工艺副边，请在副边上增加分流点" at 7664,-786 h120
  text "2." at 7538.89,-916 h120
  text "请用供应商UL认证号，防火等级，CTI等级，生产周期替换板上的UR标识，且保持其位置、方向一致," at 7664,-916 h120
  text "若板内无，可在工艺副边添加; 禁止添加文件中不存在的元素，包括供应商LOGO、无铅、光学基准点等" at 7664,-1045.66 h120
  text "3." at 7539,-1176 h120
  text "若焊盘开窗与丝印油冲突，焊盘处需将丝印油掏开，不允许上盘" at 7664,-1176 h120
  text "4." at 7539,-1296 h120
  text "若存在V-CUT，无特别说明时，须为双面V-CUT，角度30（+-5°），余量按以下表格执行" at 7664,-1296 h120
  text "PCB厚度（mm）" at 8095,-1471 h120
  text "筋厚" at 7760,-1486 h120
  text "（余量）" at 7710,-1606 h120
  text "0.6" at 8095,-1611 h120
  text "0.8" at 8334.62,-1611 h120
  text "1" at 8630.92,-1611 h120
  text "1.2" at 8815,-1611 h120
  text "1.6" at 9055,-1611 h120
  text "2" at 9340,-1611 h120
  text "2.5" at 9534.39,-1611 h120
  text "3" at 9820,-1611 h120
  text "0.16" at 8065.14,-1748.5 h120
  text "0.2" at 8335.14,-1748.5 h120
  text "0.3" at 8575.14,-1748.5 h120
  text "0.3" at 8811,-1748.5 h120
  text "0.4" at 9051.52,-1748.5 h120
  text "0.5" at 9295.29,-1748.5 h120
  text "0.5" at 9535.14,-1748.5 h120
  text "最小值" at 7705,-1751 h120
  text "0.5" at 9774,-1751 h120
  text "0.32" at 8065.54,-1886 h120
  text "0.4" at 8334.85,-1886 h120
  text "0.45" at 8544.99,-1886 h120
  text "0.5" at 8810.72,-1886 h120
  text "0.6" at 9054,-1886 h120
  text "0.7" at 9295.58,-1886 h120
  text "0.8" at 9535.31,-1886 h120
  text "0.8" at 9775.12,-1886 h120
  text "最大值" at 7705,-1891 h120
  text "5." at 7539,-2061 h120
  text "PCB做完后，请高温烘烤进行应力释放，再整平（或重物压板烘烤），防止翘曲" at 7664,-2061 h120
  text "我司生产使用无铅工艺制程" at 7659,-2196 h120
  text "6." at 7539,-2201 h120
Drill Drawing:
  text ".Legend" at 7460,2840.91 h60

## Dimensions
0,2244.09 to 6692.91,2244.09 on Mechanical 1
0,2244.09 to 0,-2244.09 on Mechanical 1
